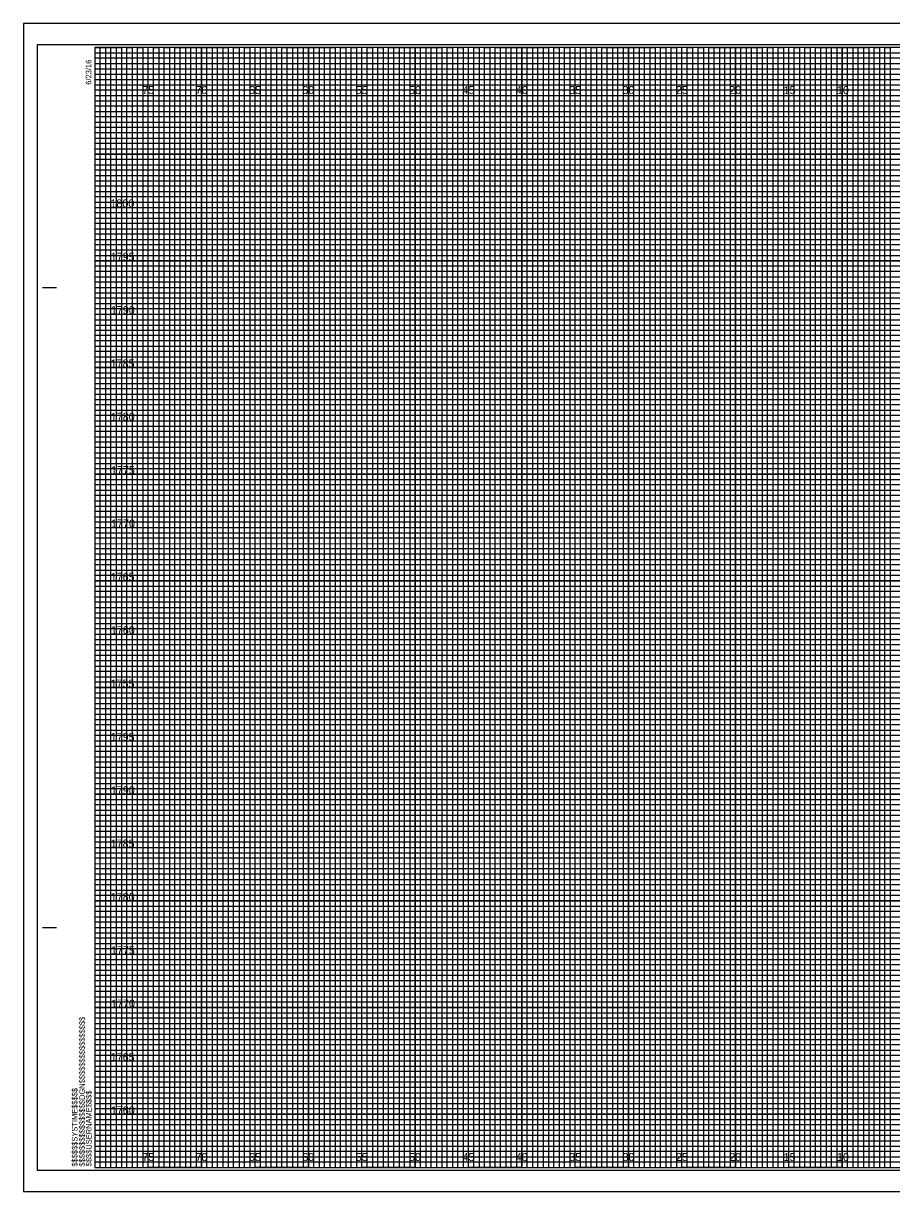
# Model space of a CAD drawing. Extents: x -7 to 162, y -2 to 767.
# Drawn here: x -6.7 to 74.6, y 547.8 to 657.2 of the extents above; entities that cross this region are included whole.
import ezdxf

# ---------------------------------------------------------------- set-up
doc = ezdxf.new("R2010")
doc.units = 0
for name, color, linetype in [('Prop Grid Mask', 7, 'Continuous'), ('Prop XS Elevation Labels', 7, 'Continuous'), ('Sheet Cross Section CELL', 7, 'Continuous'), ('Sheet Cross Section Grid Major CELL', 7, 'Continuous'), ('Sheet Cross Section Grid Middle CELL', 7, 'Continuous'), ('Sheet Cross Section Grid Minor 1 CELL', 7, 'Continuous'), ('Sheet Cross Section Grid Minor 2 CELL', 7, 'Continuous'), ('Sheet Cutting Line CELL', 7, 'Continuous'), ('Sheet DOT Grid CELL', 7, 'Continuous'), ('Sheet Plot Border Inside CELL', 7, 'Continuous'), ('Sheet Plot Border Outside CELL', 7, 'Continuous')]:
    doc.layers.add(name, color=color, linetype=linetype)

msp = doc.modelspace()

# ---------------------------------------------------------------- linework, layer by layer
at = {"layer": 'Sheet Cross Section CELL'}
for p, q in [((-4.9, 632.5), (-3.65, 632.5)), ((-4.85, 632.5), (-3.6, 632.5)), ((-4.9, 572.5), (-3.65, 572.5)), ((-4.85, 572.5), (-3.6, 572.5)), ((0, 550), (0, 550)), ((0, 550), (0, 550)), ((0, 550), (0, 550)), ((0, 550), (0, 550)), ((0, 550), (0, 550)), ((0, 550), (0, 550)), ((0, 550), (0, 550))]:
    msp.add_line(p, q, dxfattribs=at)
msp.add_lwpolyline([(160, 655), (0, 655), (0, 550), (160, 550)], close=True, dxfattribs=at)
at = {"layer": 'Sheet Cross Section Grid Major CELL'}
for p, q in [((5, 655), (0, 655)), ((5, 550), (5, 655)), ((15, 655), (10, 655)), ((10, 655), (10, 550)), ((15, 550), (15, 655)), ((25, 655), (20, 655)), ((20, 655), (20, 550)), ((25, 550), (25, 655)), ((35, 655), (30, 655)), ((30, 655), (30, 550)), ((35, 550), (35, 655)), ((45, 655), (40, 655)), ((40, 655), (40, 550)), ((45, 550), (45, 655)), ((55, 655), (50, 655)), ((50, 655), (50, 550)), ((55, 550), (55, 655)), ((65, 655), (60, 655)), ((60, 655), (60, 550)), ((65, 550), (65, 655)), ((75, 655), (70, 655)), ((70, 655), (70, 550)), ((10, 550), (5, 550)), ((20, 550), (15, 550)), ((30, 550), (25, 550)), ((40, 550), (35, 550)), ((50, 550), (45, 550)), ((60, 550), (55, 550)), ((70, 550), (65, 550))]:
    msp.add_line(p, q, dxfattribs=at)
for points in [[(0, 650), (160, 650), (160, 645), (0, 645)], [(0, 640), (160, 640), (160, 635), (0, 635)], [(0, 630), (160, 630), (160, 625), (0, 625)], [(0, 620), (160, 620), (160, 615), (0, 615)], [(0, 610), (160, 610), (160, 605), (0, 605)], [(0, 600), (160, 600), (160, 595), (0, 595)], [(0, 590), (160, 590), (160, 585), (0, 585)], [(0, 580), (160, 580), (160, 575), (0, 575)], [(0, 570), (160, 570), (160, 565), (0, 565)], [(0, 560), (160, 560), (160, 555), (0, 555)]]:
    msp.add_lwpolyline(points, dxfattribs=at)
at = {"layer": 'Sheet Cross Section Grid Middle CELL'}
for points in [[(0, 655), (2.5, 655), (2.5, 550), (7.5, 550), (7.5, 655), (12.5, 655), (12.5, 550), (17.5, 550), (17.5, 655), (22.5, 655), (22.5, 550), (27.5, 550), (27.5, 655), (32.5, 655), (32.5, 550), (37.5, 550), (37.5, 655), (42.5, 655), (42.5, 550), (47.5, 550), (47.5, 655), (52.5, 655), (52.5, 550), (57.5, 550), (57.5, 655), (62.5, 655), (62.5, 550), (67.5, 550), (67.5, 655), (72.5, 655), (72.5, 550), (77.5, 550)], [(0, 652.5), (137.5, 652.5)], [(0, 642.5), (160, 642.5), (160, 647.5), (0, 647.5)], [(0, 632.5), (160, 632.5), (160, 637.5), (0, 637.5)], [(0, 622.5), (160, 622.5), (160, 627.5), (0, 627.5)], [(0, 612.5), (160, 612.5), (160, 617.5), (0, 617.5)], [(0, 602.5), (160, 602.5), (160, 607.5), (0, 607.5)], [(0, 592.5), (160, 592.5), (160, 597.5), (0, 597.5)], [(0, 582.5), (160, 582.5), (160, 587.5), (0, 587.5)], [(0, 572.5), (160, 572.5), (160, 577.5), (0, 577.5)], [(0, 562.5), (160, 562.5), (160, 567.5), (0, 567.5)], [(0, 552.5), (160, 552.5), (160, 557.5), (0, 557.5)]]:
    msp.add_lwpolyline(points, dxfattribs=at)
at = {"layer": 'Sheet Cross Section Grid Minor 1 CELL'}
for p, q in [((0, 654.5), (130, 654.5)), ((130, 653.99), (0, 653.99)), ((0, 653.99), (0, 653.5)), ((0, 653.5), (130, 653.5)), ((130, 652.95), (0, 652.95)), ((0, 652.95), (0, 652)), ((0, 652), (160, 652))]:
    msp.add_line(p, q, dxfattribs=at)
for points in [[(0, 651.5), (135, 651.5), (160, 651.5), (160, 651), (0, 651)], [(0, 650.5), (160, 650.5), (160, 649.5), (0, 649.5)], [(0, 649), (160, 649), (160, 648.5), (0, 648.49)], [(0, 648), (160, 648), (160, 647), (0, 647)], [(0, 646.5), (160, 646.5), (160, 646), (0, 646)], [(0, 645.5), (160, 645.5), (160, 644.5), (0, 644.5)], [(0, 644), (160, 644), (160, 643.5), (0, 643.5)], [(0, 643), (160, 643), (160, 642), (0, 642)], [(0, 641.5), (160, 641.5), (160, 641), (0, 641)], [(0, 640.5), (160, 640.5), (160, 639.5), (0, 639.5)], [(0, 639), (160, 639), (160, 638.5), (0, 638.5)], [(0, 638), (160, 638), (160, 636.98), (160, 636.5), (160, 636), (0, 636)], [(0, 637), (160, 637), (160, 636.5), (0, 636.5)], [(0, 635.5), (160, 635.5), (160, 634.5), (0, 634.51)], [(0, 634.51), (160, 634.5), (160, 634), (0, 634)], [(0, 633.5), (160, 633.5), (160, 633), (0, 633)], [(0, 632), (160, 632), (160, 631.5), (0, 631.5)], [(0, 631), (160, 631), (160, 630.5), (0, 630.5)], [(-0.04, 629.45), (160, 629.45), (160, 628.94), (-0.04, 628.94)], [(0, 628.5), (160, 628.5), (160, 628), (0, 628)], [(0, 627), (160, 627), (160, 626.5), (0, 626.5)], [(0, 626), (160, 626), (160, 625.5), (0, 625.5)], [(0, 624.5), (160, 624.5), (160, 624), (0, 624)], [(0, 623.5), (160, 623.5), (160, 623), (0, 623)], [(0, 622), (160, 622), (160, 621.5), (0, 621.5)], [(0, 621), (160, 621), (160, 620.5), (0, 620.5)], [(0, 619.5), (160, 619.5), (160, 618.99), (0, 619)], [(0, 618.5), (160, 618.5), (160, 618), (0, 618)], [(0, 617), (160, 617), (160, 616.5), (0, 616.5)], [(0, 616), (160, 616), (160, 615.5), (0, 615.5)], [(0, 614.5), (160, 614.5), (160, 614), (0, 614)], [(0, 613.5), (160, 613.5), (160, 613), (0, 613)], [(0, 612), (160, 612), (160, 611.5), (0, 611.5)], [(0, 611), (160, 611), (160, 610.5), (0, 610.5)], [(0, 609.5), (160, 609.5), (160, 609), (0, 609)], [(0, 608.5), (160.03, 608.46), (160, 608), (0, 608)], [(0, 607), (160, 607), (160, 606.5), (0, 606.5)], [(0, 606), (160, 606), (160, 605.5), (0, 605.5)], [(0, 604.5), (160, 604.5), (160, 604), (0, 604)], [(0, 603.5), (160, 603.5), (160, 603), (0, 603)], [(0, 602), (160, 602), (160, 601.5), (0, 601.5)], [(0, 601), (160, 601), (160, 600.5), (0, 600.5)], [(0, 599.5), (160, 599.5), (160, 599), (0, 599)], [(0, 598.5), (160, 598.5), (160, 598), (0, 598)], [(0, 597), (160, 597), (160, 596.5), (0, 596.5)], [(0, 596), (160, 596), (160, 595.5), (0, 595.5)], [(0, 594.5), (160, 594.5), (160, 594), (0, 594)], [(0, 593.5), (160, 593.5), (160, 593), (0, 593)], [(0, 592), (160, 592), (160, 591.5), (0, 591.5)], [(0, 591), (160, 591), (160, 590.5), (0, 590.5)], [(0, 589.5), (160, 589.5), (160, 588.99), (0, 589)], [(0, 588.5), (160, 588.5), (160, 588), (0, 588)], [(0, 587), (160, 587), (160, 586.5), (0, 586.5)], [(0, 586), (160, 586), (160, 585.5), (0, 585.5)], [(0, 584.5), (160, 584.5), (160, 584), (0, 584)], [(0, 583.5), (160, 583.5), (160, 583), (0, 583)], [(0, 582), (160, 582), (160, 581.5), (0, 581.5)], [(0, 581), (160, 581), (160, 580.5), (0, 580.5)], [(0, 579.5), (160, 579.5), (160, 579), (0, 579)], [(0, 578.5), (160.03, 578.46), (160, 578), (0, 578)], [(0, 577), (160, 577), (160, 576.5), (0, 576.5)], [(0, 576), (160, 576), (160, 575.5), (0, 575.5)], [(0, 574.5), (160, 574.5), (160, 574), (0, 574)], [(0, 573.5), (160, 573.5), (160, 573), (0, 573)], [(0, 572), (160, 572), (160, 571.5), (0, 571.5)], [(0, 571), (160, 571), (160, 570.5), (0, 570.5)], [(0, 569.5), (160, 569.5), (160, 569), (0, 569)], [(0, 568.5), (160, 568.5), (160, 568), (0, 568)], [(0, 567), (160, 567), (160, 566.5), (0, 566.5)], [(0, 566), (160, 566), (160, 565.5), (0, 565.5)], [(0, 564.5), (160, 564.5), (160, 564), (0, 564)], [(0, 563.5), (160, 563.5), (160, 563), (0, 563)], [(0, 562), (160, 562), (160, 561.5), (0, 561.5)], [(0, 561), (160, 561), (160, 560.5), (0, 560.5)], [(0, 559.5), (160, 559.5), (160, 559), (0, 559)], [(0, 558.5), (160, 558.5), (160, 558), (0, 558)], [(0, 557), (160, 557), (160, 556.5), (0, 556.5)], [(0, 556), (160, 556), (160, 555.5), (0, 555.5)], [(0, 554.5), (160, 554.5), (160, 554), (0, 554)], [(0, 553.5), (160, 553.5), (160, 553), (0, 553)], [(0, 552), (160, 552), (160, 551.5), (0, 551.5)], [(0, 551), (160, 551), (160, 550.5), (0, 550.5)]]:
    msp.add_lwpolyline(points, dxfattribs=at)
at = {"layer": 'Sheet Cross Section Grid Minor 2 CELL'}
for points in [[(0, 550), (0.5, 550), (0.5, 655), (1, 655), (1, 550)], [(1, 550), (1.5, 550), (1.5, 655), (2, 655), (2, 550)], [(2.5, 550), (3, 550), (3, 655), (3.5, 655), (3.5, 550)], [(3.5, 550), (4, 550), (4, 655), (4.5, 655), (4.5, 550)], [(5, 550), (5.5, 550), (5.5, 655), (6, 655), (6, 550)], [(6, 550), (6.5, 550), (6.5, 655), (7, 655), (7, 550)], [(7.5, 550), (8, 550), (8, 655), (8.5, 655), (8.5, 550)], [(8.5, 550), (9, 550), (9, 655), (9.5, 655), (9.5, 550)], [(10, 550), (10.5, 550), (10.5, 655), (11, 655), (11, 550)], [(11, 550), (11.5, 550), (11.5, 655), (12, 655), (12, 550)], [(12.5, 550), (13, 550), (13, 655), (13.5, 655), (13.5, 550)], [(13.5, 550), (14, 550), (14, 655), (14.5, 655), (14.5, 550)], [(15, 550), (15.5, 550), (15.5, 655), (16, 655), (16, 550)], [(16, 550), (16.5, 550), (16.5, 655), (17, 655), (17, 550)], [(17.5, 550), (18, 550), (18, 655), (18.5, 655), (18.5, 550)], [(18.5, 550), (19, 550), (19, 655), (19.5, 655), (19.5, 550)], [(20, 550), (20.5, 550), (20.5, 655), (21, 655), (21, 550)], [(21, 550), (21.5, 550), (21.5, 655), (22, 655), (22, 550)], [(22.5, 550), (23, 550), (23, 655), (23.5, 655), (23.5, 550)], [(23.5, 550), (24, 550), (24, 655), (24.5, 655), (24.5, 550)], [(25, 550), (25.5, 550), (25.5, 655), (26, 655), (26, 550)], [(26, 550), (26.5, 550), (26.5, 655), (27, 655), (27, 550)], [(27.5, 550), (28, 550), (28, 655), (28.5, 655), (28.5, 550)], [(28.5, 550), (29, 550), (29, 655), (29.5, 655), (29.5, 550)], [(30, 550), (30.5, 550), (30.5, 655), (31, 655), (31, 550)], [(31, 550), (31.5, 550), (31.5, 655), (32, 655), (32, 550)], [(32.5, 550), (33, 550), (33, 655), (33.5, 655), (33.5, 550)], [(33.5, 550), (34, 550), (34, 655), (34.5, 655), (34.5, 550)], [(35, 550), (35.5, 550), (35.5, 655), (36, 655), (36, 550)], [(36, 550), (36.5, 550), (36.5, 655), (37, 655), (37, 550)], [(37.5, 550), (38, 550), (38, 655), (38.5, 655), (38.5, 550)], [(38.5, 550), (39, 550), (39, 655), (39.5, 655), (39.5, 550)], [(40, 550), (40.5, 550), (40.5, 655), (41, 655), (41, 550)], [(41, 550), (41.5, 550), (41.5, 655), (42, 655), (42, 550)], [(42.5, 550), (43, 550), (43, 655), (43.5, 655), (43.5, 550)], [(43.5, 550), (44, 550), (44, 655), (44.5, 655), (44.5, 550)], [(45, 550), (45.5, 550), (45.5, 655), (46, 655), (46, 550)], [(46, 550), (46.5, 550), (46.5, 655), (47, 655), (47, 550)], [(47.5, 550), (48, 550), (48, 655), (48.5, 655), (48.5, 550)], [(48.5, 550), (49, 550), (49, 655), (49.5, 655), (49.5, 550)], [(50, 550), (50.5, 550), (50.5, 655), (51, 655), (51, 550)], [(51, 550), (51.5, 550), (51.5, 655), (52, 655), (52, 550)], [(52.5, 550), (53, 550), (53, 655), (53.5, 655), (53.5, 550)], [(53.5, 550), (54, 550), (54, 655), (54.5, 655), (54.5, 550)], [(55, 550), (55.5, 550), (55.5, 655), (56, 655), (56, 550)], [(56, 550), (56.5, 550), (56.5, 655), (57, 655), (57, 550)], [(57.5, 550), (58, 550), (58, 655), (58.5, 655), (58.5, 550)], [(58.5, 550), (59, 550), (59, 655), (59.5, 655), (59.5, 550)], [(60, 550), (60.5, 550), (60.5, 655), (61, 655), (61, 550)], [(61, 550), (61.5, 550), (61.5, 655), (62, 655), (62, 550)], [(62.5, 550), (63, 550), (63, 655), (63.5, 655), (63.5, 550)], [(63.5, 550), (64, 550), (64, 655), (64.5, 655), (64.5, 550)], [(65, 550), (65.5, 550), (65.5, 655), (66, 655), (66, 550)], [(66, 550), (66.5, 550), (66.5, 655), (67, 655), (67, 550)], [(67.5, 550), (68, 550), (68, 655), (68.5, 655), (68.5, 550)], [(68.5, 550), (69, 550), (69, 655), (69.5, 655), (69.5, 550)], [(70, 550), (70.5, 550), (70.5, 655), (71, 655), (71, 550)], [(71, 550), (71.5, 550), (71.5, 655), (72, 655), (72, 550)], [(72.5, 550), (73, 550), (73, 655), (73.5, 655), (73.5, 550)], [(73.5, 550), (74, 550), (74, 655), (74.5, 655), (74.5, 550)]]:
    msp.add_lwpolyline(points, dxfattribs=at)
at = {"layer": 'Sheet Cutting Line CELL'}
for p, q in [((161.65, 657.25), (-6.7, 657.25)), ((-6.7, 657.25), (-6.7, 547.75)), ((-6.7, 547.75), (161.65, 547.75))]:
    msp.add_line(p, q, dxfattribs=at)
at = {"layer": 'Sheet DOT Grid CELL'}
for p, q in [((5, 550), (5, 655)), ((10, 550), (10, 655)), ((15, 550), (15, 655)), ((20, 550), (20, 655)), ((25, 550), (25, 655)), ((30, 550), (30, 655)), ((35, 550), (35, 655)), ((40, 550), (40, 655)), ((45, 550), (45, 655)), ((50, 550), (50, 655)), ((55, 550), (55, 655)), ((60, 550), (60, 655)), ((65, 550), (65, 655)), ((70, 550), (70, 655)), ((0, 650), (160, 650)), ((0, 645), (160, 645)), ((0, 640), (160, 640)), ((0, 635), (160, 635)), ((0, 630), (160, 630)), ((0, 625), (160, 625)), ((0, 620), (160, 620)), ((0, 615), (160, 615)), ((0, 610), (160, 610)), ((0, 605), (160, 605)), ((0, 600), (160, 600)), ((0, 595), (160, 595)), ((0, 590), (160, 590)), ((0, 585), (160, 585)), ((0, 580), (160, 580)), ((0, 575), (160, 575)), ((0, 570), (160, 570)), ((0, 565), (160, 565)), ((0, 560), (160, 560)), ((0, 555), (160, 555))]:
    msp.add_line(p, q, dxfattribs=at)
at = {"layer": 'Sheet Plot Border Inside CELL'}
msp.add_lwpolyline([(-5.4, 549.75), (161.2, 549.75), (161.2, 655.25), (-5.4, 655.25)], close=True, dxfattribs=at)
at = {"layer": 'Sheet Plot Border Outside CELL'}
msp.add_lwpolyline([(-6.7, 547.75), (161.65, 547.75), (161.65, 657.25), (-6.7, 657.25)], close=True, dxfattribs=at)

# ---------------------------------------------------------------- texts
at = {"layer": 'Prop Grid Mask'}
for s, p in [('75', (4.44, 650.62)), ('70', (9.43, 650.62)), ('65', (14.44, 650.62)), ('60', (19.43, 650.62)), ('55', (24.44, 650.62)), ('50', (29.43, 650.62)), ('45', (34.44, 650.62)), ('40', (39.43, 650.62)), ('35', (44.44, 650.62)), ('30', (49.43, 650.62)), ('25', (54.44, 650.62)), ('20', (59.43, 650.62)), ('15', (64.53, 650.62)), ('10', (69.52, 650.62)), ('75', (4.44, 550.62)), ('70', (9.43, 550.62)), ('65', (14.44, 550.62)), ('60', (19.43, 550.62)), ('55', (24.44, 550.62)), ('50', (29.43, 550.62)), ('45', (34.44, 550.62)), ('40', (39.43, 550.62)), ('35', (44.44, 550.62)), ('30', (49.43, 550.62)), ('25', (54.44, 550.62)), ('20', (59.43, 550.62)), ('15', (64.53, 550.62)), ('10', (69.52, 550.62))]:
    msp.add_text(s, height=0.75, dxfattribs=at).set_placement(p)
at = {"layer": 'Prop XS Elevation Labels'}
for s, p in [('1800', (1.46, 640)), ('1795', (1.49, 635)), ('1790', (1.5, 630)), ('1785', (1.48, 625)), ('1780', (1.49, 620)), ('1775', (1.51, 615)), ('1770', (1.52, 610)), ('1765', (1.49, 605)), ('1760', (1.5, 600)), ('1755', (1.47, 595)), ('1795', (1.49, 590)), ('1790', (1.5, 585)), ('1785', (1.48, 580)), ('1780', (1.49, 575)), ('1775', (1.51, 570)), ('1770', (1.52, 565)), ('1765', (1.49, 560)), ('1760', (1.5, 555))]:
    msp.add_text(s, height=0.75, dxfattribs=at).set_placement(p)
at = {"layer": 'Sheet Cross Section CELL'}
for s, p in [('6/23/16', (-0.33, 651.5)), ('$$$$$$$$$$$$$$$$DGN$$$$$$$$$$$$$$$$', (-0.94, 550.09)), ('$$$$$$SYSTIME$$$$$', (-1.63, 550.09)), ('$$$$USERNAME$$$$', (-0.31, 550.12))]:
    msp.add_text(s, height=0.525, rotation=90, dxfattribs=at).set_placement(p)

doc.saveas('drawing.dxf')
